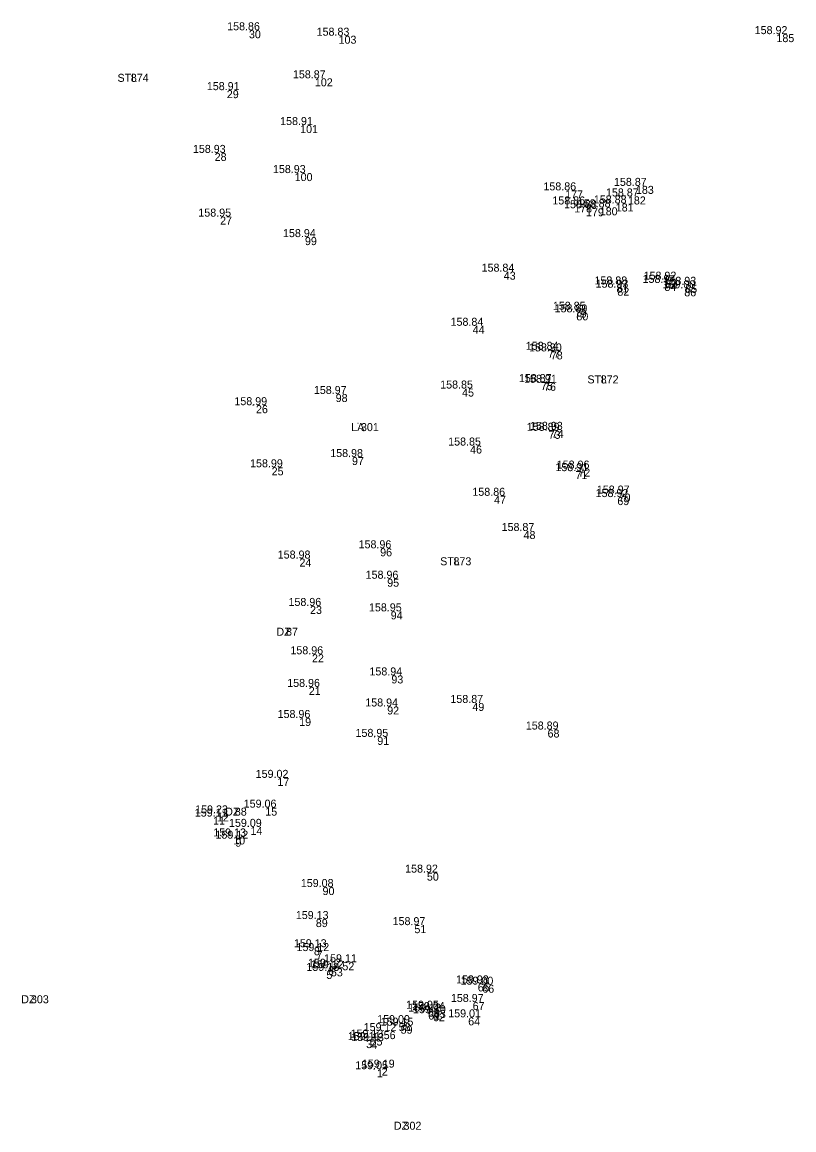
# Model space of a CAD drawing. Extents: x -583198 to -582878, y -1211024 to -1210637.
# Drawn here: x -583175.77 to -583151.66, y -1211024.36 to -1210989.77 of the extents above; entities that cross this region are included whole.
import ezdxf

# ---------------------------------------------------------------- set-up
doc = ezdxf.new("R2010")
doc.units = 0
for name, color, linetype in [('1   Kódy', 7, 'Continuous'), ('4   Body podrobné', 7, 'Continuous'), ('5   Body podrobné - čísla', 7, 'Continuous'), ('6   Body podrobné - výšky', 7, 'Continuous')]:
    doc.layers.add(name, color=color, linetype=linetype)

msp = doc.modelspace()

# ---------------------------------------------------------------- linework, layer by layer
at = {"layer": '4   Body podrobné'}
for p, q in [((-583168.78, -1210990.02), (-583168.779, -1210990.02)), ((-583165.98, -1210990.19), (-583165.979, -1210990.19)), ((-583152.3, -1210990.14), (-583152.299, -1210990.14)), ((-583172.47, -1210991.38), (-583172.469, -1210991.38)), ((-583166.72, -1210991.52), (-583166.719, -1210991.52)), ((-583169.47, -1210991.89), (-583169.469, -1210991.89)), ((-583167.18, -1210992.98), (-583167.179, -1210992.98)), ((-583169.85, -1210993.85), (-583169.849, -1210993.85)), ((-583167.35, -1210994.48), (-583167.349, -1210994.48)), ((-583156.69, -1210994.88), (-583156.689, -1210994.88)), ((-583158.9, -1210995.02), (-583158.899, -1210995.02)), ((-583156.94, -1210995.21), (-583156.939, -1210995.21)), ((-583158.62, -1210995.46), (-583158.619, -1210995.46)), ((-583158.25, -1210995.58), (-583158.249, -1210995.58)), ((-583157.82, -1210995.55), (-583157.819, -1210995.55)), ((-583157.32, -1210995.43), (-583157.319, -1210995.43)), ((-583169.68, -1210995.84), (-583169.679, -1210995.84)), ((-583167.03, -1210996.48), (-583167.029, -1210996.48)), ((-583160.82, -1210997.56), (-583160.819, -1210997.56)), ((-583157.3, -1210997.96), (-583157.299, -1210997.96)), ((-583155.8, -1210997.91), (-583155.799, -1210997.91)), ((-583155.77, -1210997.81), (-583155.769, -1210997.81)), ((-583155.15, -1210997.97), (-583155.149, -1210997.97)), ((-583157.27, -1210998.06), (-583157.269, -1210998.06)), ((-583155.18, -1210998.08), (-583155.179, -1210998.08)), ((-583158.6, -1210998.75), (-583158.599, -1210998.75)), ((-583158.55, -1210998.83), (-583158.549, -1210998.83)), ((-583161.79, -1210999.25), (-583161.789, -1210999.25)), ((-583159.44, -1211000), (-583159.439, -1211000)), ((-583159.35, -1211000.05), (-583159.349, -1211000.05)), ((-583159.66, -1211001.01), (-583159.659, -1211001.01)), ((-583159.56, -1211001.03), (-583159.559, -1211001.03)), ((-583157.79, -1211000.8), (-583157.789, -1211000.8)), ((-583166.07, -1211001.38), (-583166.069, -1211001.38)), ((-583162.12, -1211001.21), (-583162.119, -1211001.21)), ((-583168.56, -1211001.73), (-583168.559, -1211001.73)), ((-583165.28, -1211002.29), (-583165.279, -1211002.29)), ((-583159.32, -1211002.5), (-583159.319, -1211002.5)), ((-583159.42, -1211002.53), (-583159.419, -1211002.53)), ((-583161.87, -1211002.99), (-583161.869, -1211002.99)), ((-583165.56, -1211003.35), (-583165.559, -1211003.35)), ((-583168.07, -1211003.67), (-583168.069, -1211003.67)), ((-583158.58, -1211003.79), (-583158.579, -1211003.79)), ((-583158.49, -1211003.71), (-583158.489, -1211003.71)), ((-583161.12, -1211004.56), (-583161.119, -1211004.56)), ((-583157.23, -1211004.49), (-583157.229, -1211004.49)), ((-583157.27, -1211004.6), (-583157.269, -1211004.6)), ((-583160.2, -1211005.66), (-583160.199, -1211005.66)), ((-583164.68, -1211006.2), (-583164.679, -1211006.2)), ((-583167.2, -1211006.52), (-583167.199, -1211006.52)), ((-583162.39, -1211006.48), (-583162.389, -1211006.48)), ((-583164.46, -1211007.15), (-583164.459, -1211007.15)), ((-583166.87, -1211008), (-583166.869, -1211008)), ((-583164.35, -1211008.17), (-583164.349, -1211008.17)), ((-583167.62, -1211008.68), (-583167.619, -1211008.68)), ((-583166.81, -1211009.51), (-583166.809, -1211009.51)), ((-583164.33, -1211010.17), (-583164.329, -1211010.17)), ((-583166.91, -1211010.53), (-583166.909, -1211010.53)), ((-583164.46, -1211011.14), (-583164.459, -1211011.14)), ((-583161.8, -1211011.03), (-583161.799, -1211011.03)), ((-583167.21, -1211011.5), (-583167.209, -1211011.5)), ((-583159.45, -1211011.86), (-583159.449, -1211011.86)), ((-583164.77, -1211012.09), (-583164.769, -1211012.09)), ((-583167.89, -1211013.37), (-583167.889, -1211013.37)), ((-583169.9, -1211014.58), (-583169.899, -1211014.58)), ((-583169.78, -1211014.48), (-583169.779, -1211014.48)), ((-583169.22, -1211014.3), (-583169.219, -1211014.3)), ((-583168.27, -1211014.3), (-583168.269, -1211014.3)), ((-583168.73, -1211014.9), (-583168.729, -1211014.9)), ((-583169.27, -1211015.2), (-583169.269, -1211015.2)), ((-583169.2, -1211015.27), (-583169.199, -1211015.27)), ((-583163.22, -1211016.33), (-583163.219, -1211016.33)), ((-583166.48, -1211016.78), (-583166.479, -1211016.78)), ((-583166.69, -1211017.78), (-583166.689, -1211017.78)), ((-583163.61, -1211017.97), (-583163.609, -1211017.97)), ((-583166.75, -1211018.66), (-583166.749, -1211018.66)), ((-583166.67, -1211018.78), (-583166.669, -1211018.78)), ((-583165.86, -1211019.13), (-583165.859, -1211019.13)), ((-583166.36, -1211019.4), (-583166.359, -1211019.4)), ((-583166.31, -1211019.27), (-583166.309, -1211019.27)), ((-583166.22, -1211019.32), (-583166.219, -1211019.32)), ((-583161.63, -1211019.79), (-583161.629, -1211019.79)), ((-583175.59, -1211020.16), (-583175.589, -1211020.16)), ((-583161.49, -1211019.83), (-583161.489, -1211019.83)), ((-583161.79, -1211020.37), (-583161.789, -1211020.37)), ((-583163.19, -1211020.58), (-583163.189, -1211020.58)), ((-583163.18, -1211020.67), (-583163.179, -1211020.67)), ((-583163.03, -1211020.72), (-583163.029, -1211020.72)), ((-583163, -1211020.62), (-583162.999, -1211020.62)), ((-583161.93, -1211020.85), (-583161.929, -1211020.85)), ((-583164.1, -1211021.03), (-583164.099, -1211021.03)), ((-583164.04, -1211021.11), (-583164.039, -1211021.11)), ((-583164.98, -1211021.48), (-583164.979, -1211021.48)), ((-583164.57, -1211021.28), (-583164.569, -1211021.28)), ((-583165.12, -1211021.56), (-583165.119, -1211021.56)), ((-583164.96, -1211021.59), (-583164.959, -1211021.59)), ((-583164.78, -1211022.47), (-583164.779, -1211022.47)), ((-583164.63, -1211022.42), (-583164.629, -1211022.42)), ((-583163.95, -1211024.11), (-583163.949, -1211024.11))]:
    msp.add_line(p, q, dxfattribs=at)

# ---------------------------------------------------------------- texts
at = {"layer": '1   Kódy'}
for s, p in [('STL', (-583172.792, -1210991.63)), ('STL', (-583158.112, -1211001.05)), ('LA', (-583165.49, -1211002.54)), ('STL', (-583162.712, -1211006.73)), ('DZ', (-583167.829, -1211008.93)), ('DZ', (-583169.429, -1211014.55)), ('DZ', (-583175.799, -1211020.41)), ('DZ', (-583164.159, -1211024.36))]:
    msp.add_text(s, height=0.25, dxfattribs=at).set_placement(p)
at = {"layer": '5   Body podrobné - čísla'}
for s, p in [(' 30', (-583168.78, -1210990.27)), (' 103', (-583165.98, -1210990.44)), (' 185', (-583152.3, -1210990.39)), (' 874', (-583172.47, -1210991.63)), (' 102', (-583166.72, -1210991.77)), (' 29', (-583169.47, -1210992.14)), (' 101', (-583167.18, -1210993.23)), (' 28', (-583169.85, -1210994.1)), (' 100', (-583167.35, -1210994.73)), (' 183', (-583156.69, -1210995.13)), (' 177', (-583158.9, -1210995.27)), (' 182', (-583156.94, -1210995.46)), (' 178', (-583158.62, -1210995.71)), (' 179', (-583158.25, -1210995.83)), (' 180', (-583157.82, -1210995.8)), (' 181', (-583157.32, -1210995.68)), (' 27', (-583169.68, -1210996.09)), (' 99', (-583167.03, -1210996.73)), (' 43', (-583160.82, -1210997.81)), (' 81', (-583157.3, -1210998.21)), (' 84', (-583155.8, -1210998.16)), (' 83', (-583155.77, -1210998.06)), (' 85', (-583155.15, -1210998.22)), (' 82', (-583157.27, -1210998.31)), (' 86', (-583155.18, -1210998.33)), (' 79', (-583158.6, -1210999)), (' 80', (-583158.55, -1210999.08)), (' 44', (-583161.79, -1210999.5)), (' 77', (-583159.44, -1211000.25)), (' 78', (-583159.35, -1211000.3)), (' 75', (-583159.66, -1211001.26)), (' 76', (-583159.56, -1211001.28)), (' 872', (-583157.79, -1211001.05)), (' 98', (-583166.07, -1211001.63)), (' 45', (-583162.12, -1211001.46)), (' 26', (-583168.56, -1211001.98)), (' 301', (-583165.28, -1211002.54)), (' 74', (-583159.32, -1211002.75)), (' 73', (-583159.42, -1211002.78)), (' 46', (-583161.87, -1211003.24)), (' 97', (-583165.56, -1211003.6)), (' 25', (-583168.07, -1211003.92)), (' 71', (-583158.58, -1211004.04)), (' 72', (-583158.49, -1211003.96)), (' 47', (-583161.12, -1211004.81)), (' 69', (-583157.27, -1211004.85)), (' 70', (-583157.23, -1211004.74)), (' 48', (-583160.2, -1211005.91)), (' 96', (-583164.68, -1211006.45)), (' 24', (-583167.2, -1211006.77)), (' 873', (-583162.39, -1211006.73)), (' 95', (-583164.46, -1211007.4)), (' 23', (-583166.87, -1211008.25)), (' 94', (-583164.35, -1211008.42)), (' 87', (-583167.62, -1211008.93)), (' 22', (-583166.81, -1211009.76)), (' 93', (-583164.33, -1211010.42)), (' 21', (-583166.91, -1211010.78)), (' 92', (-583164.46, -1211011.39)), (' 49', (-583161.8, -1211011.28)), (' 19', (-583167.21, -1211011.75)), (' 68', (-583159.45, -1211012.11)), (' 91', (-583164.77, -1211012.34)), (' 17', (-583167.89, -1211013.62)), (' 11', (-583169.9, -1211014.83)), (' 12', (-583169.78, -1211014.73)), (' 88', (-583169.22, -1211014.55)), (' 15', (-583168.27, -1211014.55)), (' 14', (-583168.73, -1211015.15)), (' 10', (-583169.27, -1211015.45)), (' 9', (-583169.2, -1211015.52)), (' 50', (-583163.22, -1211016.58)), (' 90', (-583166.48, -1211017.03)), (' 89', (-583166.69, -1211018.03)), (' 51', (-583163.61, -1211018.22)), (' 8', (-583166.75, -1211018.91)), (' 7', (-583166.67, -1211019.03)), (' 52', (-583165.86, -1211019.38)), (' 5', (-583166.36, -1211019.65)), (' 6', (-583166.31, -1211019.52)), (' 53', (-583166.22, -1211019.57)), (' 65', (-583161.63, -1211020.04)), (' 303', (-583175.59, -1211020.41)), (' 66', (-583161.49, -1211020.08)), (' 67', (-583161.79, -1211020.62)), (' 60', (-583163.19, -1211020.83)), (' 61', (-583163.18, -1211020.92)), (' 62', (-583163.03, -1211020.97)), (' 63', (-583163, -1211020.87)), (' 64', (-583161.93, -1211021.1)), (' 58', (-583164.1, -1211021.28)), (' 59', (-583164.04, -1211021.36)), (' 55', (-583164.98, -1211021.73)), (' 56', (-583164.57, -1211021.53)), (' 3', (-583165.12, -1211021.81)), (' 4', (-583164.96, -1211021.84)), (' 1', (-583164.78, -1211022.72)), (' 2', (-583164.63, -1211022.67)), (' 302', (-583163.95, -1211024.36))]:
    msp.add_text(s, height=0.25, dxfattribs=at).set_placement(p)
at = {"layer": '6   Body podrobné - výšky'}
for s, p in [('158.86', (-583169.367, -1210990.02)), ('158.83', (-583166.572, -1210990.19)), ('158.92', (-583152.887, -1210990.14)), ('158.87', (-583167.313, -1210991.52)), ('158.91', (-583170.002, -1210991.89)), ('158.91', (-583167.712, -1210992.98)), ('158.93', (-583170.437, -1210993.85)), ('158.93', (-583167.937, -1210994.48)), ('158.86', (-583159.487, -1210995.02)), ('158.87', (-583157.283, -1210994.88)), ('158.86', (-583159.207, -1210995.46)), ('158.88', (-583157.912, -1210995.43)), ('158.87', (-583157.533, -1210995.21)), ('158.95', (-583170.267, -1210995.84)), ('158.88', (-583158.842, -1210995.58)), ('158.88', (-583158.412, -1210995.55)), ('158.94', (-583167.622, -1210996.48)), ('158.84', (-583161.418, -1210997.56)), ('158.97', (-583156.388, -1210997.91)), ('158.92', (-583156.357, -1210997.81)), ('158.88', (-583157.892, -1210997.96)), ('158.93', (-583157.857, -1210998.06)), ('159.00', (-583155.765, -1210998.08)), ('158.93', (-583155.737, -1210997.97)), ('158.85', (-583159.192, -1210998.75)), ('158.89', (-583159.137, -1210998.83)), ('158.84', (-583162.388, -1210999.25)), ('158.84', (-583160.038, -1211000)), ('158.90', (-583159.936, -1211000.05)), ('158.87', (-583160.253, -1211001.01)), ('158.91', (-583160.092, -1211001.03)), ('158.97', (-583166.658, -1211001.38)), ('158.85', (-583162.712, -1211001.21)), ('158.99', (-583169.141, -1211001.73)), ('158.89', (-583160.007, -1211002.53)), ('158.93', (-583159.907, -1211002.5)), ('158.85', (-583162.462, -1211002.99)), ('158.98', (-583166.147, -1211003.35)), ('158.99', (-583168.651, -1211003.67)), ('158.91', (-583159.112, -1211003.79)), ('158.96', (-583159.071, -1211003.71)), ('158.97', (-583157.818, -1211004.49)), ('158.86', (-583161.707, -1211004.56)), ('158.92', (-583157.857, -1211004.6)), ('158.87', (-583160.793, -1211005.66)), ('158.96', (-583165.261, -1211006.2)), ('158.98', (-583167.787, -1211006.52)), ('158.96', (-583165.041, -1211007.15)), ('158.96', (-583167.451, -1211008)), ('158.95', (-583164.937, -1211008.17)), ('158.96', (-583167.391, -1211009.51)), ('158.94', (-583164.922, -1211010.17)), ('158.96', (-583167.491, -1211010.53)), ('158.87', (-583162.393, -1211011.03)), ('158.94', (-583165.052, -1211011.14)), ('158.96', (-583167.791, -1211011.5)), ('158.95', (-583165.357, -1211012.09)), ('158.89', (-583160.037, -1211011.86)), ('159.02', (-583168.476, -1211013.37)), ('159.23', (-583170.367, -1211014.48)), ('159.06', (-583168.85, -1211014.3)), ('159.11', (-583170.378, -1211014.58)), ('159.13', (-583169.802, -1211015.2)), ('159.09', (-583169.31, -1211014.9)), ('159.12', (-583169.732, -1211015.27)), ('158.92', (-583163.807, -1211016.33)), ('159.08', (-583167.066, -1211016.78)), ('159.13', (-583167.222, -1211017.78)), ('158.97', (-583164.198, -1211017.97)), ('159.13', (-583167.282, -1211018.66)), ('159.12', (-583167.202, -1211018.78)), ('159.12', (-583166.842, -1211019.27)), ('159.12', (-583166.752, -1211019.32)), ('159.11', (-583166.338, -1211019.13)), ('159.13', (-583166.892, -1211019.4)), ('158.98', (-583162.217, -1211019.79)), ('159.00', (-583162.075, -1211019.83)), ('158.97', (-583162.378, -1211020.37)), ('159.05', (-583163.776, -1211020.58)), ('159.12', (-583163.712, -1211020.67)), ('159.04', (-583163.591, -1211020.62)), ('159.10', (-583163.561, -1211020.72)), ('159.09', (-583164.68, -1211021.03)), ('159.15', (-583164.572, -1211021.11)), ('159.01', (-583162.461, -1211020.85)), ('159.12', (-583165.102, -1211021.28)), ('159.11', (-583165.598, -1211021.56)), ('159.13', (-583165.512, -1211021.48)), ('159.13', (-583165.492, -1211021.59)), ('159.05', (-583165.366, -1211022.47)), ('159.19', (-583165.157, -1211022.42))]:
    msp.add_text(s, height=0.25, dxfattribs=at).set_placement(p)

doc.saveas('drawing.dxf')
